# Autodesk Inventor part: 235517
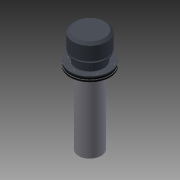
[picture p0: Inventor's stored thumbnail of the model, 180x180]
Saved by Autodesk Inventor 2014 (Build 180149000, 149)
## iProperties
Shininess: 20.0
Length Units: 11272
Angle Units: 11279
Time Units: 11290
Mass Units: 11286
Length Display Precision: 3
Angle Display Precision: 2
Company: Autodesk, Inc.
Created: 2002-06
Part Number: 235517
Material: AL 2024-T4
Description: FILLER BREATHER
Document SubType Name: Modeling
Designer: Autodesk, Inc.
Density: 2.78 g/cm^3
Mass: 669.093 g
Surface Area: 882.995 cm^2
Volume: 240.681 cm^3
Appearance: Metal-AL-6061(Flat)
Density: 0.0
Volumn: 0.0
Area: 0.0
PropertySet Name: Model Information
Control State: 0
Master: False
Checked Out: False
Last Check In By: JT
Last Check In Date: 2003-06-20
Title: FILLER BREATHER
Author: Autodesk, Inc.
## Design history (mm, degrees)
sketch "Sketch1"
  geometry: L1 (0, 0)-(0, -187.41); L2 (0, -169.863)-(0, -169.863); L3 (0, 0)-(-41.275, 0); L4 (-41.275, 0)-(-41.275, 2.381); L5 (-41.275, 2.381)-(-28.575, 2.381); L6 (-28.575, 2.381)-(-28.575, 15.081); L7 (-28.575, 15.081)-(-27.781, 15.081); L8 (-27.781, 15.081)-(-27.781, 18.256); L9 (-27.781, 18.256)-(-33.338, 18.256); L10 (-33.338, 18.256)-(-33.338, 21.431); L11 (-33.338, 21.431)-(-22.225, 21.431); L12 (-22.225, 21.431)-(-22.225, 24.606); L13 (-22.225, 24.606)-(-34.925, 24.606); L14 (-34.925, 24.606)-(-34.925, 53.181); L15 (-34.925, 53.181)-(-30.162, 57.944); L16 (-30.162, 57.944)-(0, 57.944); L17 (0, 57.944)-(0, 0); L18 (0, 0)-(0, 124.882)
  constraints: 36 end point, 10 parallel, 4 perpendicular, 2 collinear, 1 vertical, 1 vertical alignment
  dimensions: "d11" = 2.38125 distance of L3.end L4.end; "d12" = 12.7 distance of L5.end L6.end; "d13" = 3.175 distance of L7.end L8.end; "d14" = 3.175 distance of L9.end L10.end; "d15" = 3.175 distance of L11.end L12.end; "d16" = 33.3375 distance between parallel lines of L16 L13; "d17" = 4.7625 horizontal distance of L14.end L15.end; "d18" = 45 deg angle of L16 L15; "d19" = 57.15 diameter of L6 L1; "d20" = 55.5625 diameter of L8 L1; "d21" = 66.675 diameter of L10 L1; "d22" = 44.45 diameter of L12 L1; "d23" = 69.85 diameter of L14 L18; "d35" = 82.55 diameter of L4 L1
revolve "Revolution1" sketch "Sketch1" stored, may be unused: angle "d24" = 90 deg
sketch "Sketch2"
  geometry: L1 (-3.175, 41.275)-(-4.763, 41.275); L2 (-4.763, 41.275)-(-4.763, 23.813); L3 (-4.763, 23.813)-(-157.162, 23.812); L4 (-160.337, 20.637)-(-160.338, 0); L5 (-160.338, 0)-(-159.322, 0); L6 (-159.322, 0)-(-159.322, 20.51); L7 (-157.036, 22.796)-(-3.175, 22.797); L8 (-3.175, 22.797)-(-3.175, 41.275); L9 (0, 0)-(-147.629, 0); A1 r 3.175 centre (-157.162, 20.637) between (-157.162, 23.812) and (-160.337, 20.637); A2 r 2.286 centre (-157.036, 20.51) between (-157.036, 22.796) and (-159.322, 20.51)
  constraints: 18 end point, 5 parallel, 4 point on circle, 4 tangent, 3 perpendicular, 2 centre point, 1 horizontal, 1 horizontal alignment
  dimensions: "d25" = 3.175 radius of A1; "d26" = 2.286 radius of A2; "d27" = 1.016 distance between parallel lines of L4 L6; "d28" = 1.016 distance between parallel lines of L3 L7; "d29" = 1.5875 distance between parallel lines of L8 L2; "d30" = 3.175 distance from line of L9.start L8; "d31" = 82.55 diameter of L1 L9; "d32" = 47.625 diameter of L3 L9; "d33" = 155.575 distance between parallel lines of L2 L4
revolve "Revolution2" sketch "Sketch2" stored, may be unused: angle "d34" = 90 deg
sketch "Sketch3"
  geometry: L1 (0, -41.275)-(0, 41.275) reference; L2 (-3.175, -41.275)-(-3.175, 41.275) reference; L3 (0, 0)-(-23.797, 0); L4 (-3.175, 41.25)-(-3.175, 28.55); L5 (-3.175, 28.55)-(0, 28.55); L6 (-7.938, 41.25)-(-7.938, 28.55); L7 (-7.938, 28.55)-(-3.175, 28.55); L8 (-7.938, 41.25)-(-3.175, 41.25); L9 (0, 28.55)-(0, 41.25); L10 (-3.175, 41.25)-(0, 41.25); L11 (-4.762, -41.275)-(-4.763, 41.275) reference; L12 (-4.763, 41.275)-(-3.175, 41.275) reference; L13 (-4.763, 41.275)-(-3.175, 41.275) reference; L14 (-4.763, 41.275)-(-3.175, 41.275) reference; 2 further points
  constraints: 16 end point, 6 perpendicular, 3 point on line, 2 collinear, 1 horizontal alignment, 1 parallel, 1 other
  dimensions: "d36" = 3.175 distance of L1.end L4.start; "d41" = 0.0254 distance from line of L2.end L8; "d42" = 12.7 distance of L6.start L6.end; "d54" = 3.175 distance between parallel lines of L11 L6
revolve "Revolution3" sketch "Sketch3" stored, may be unused: angle "d39" = 90 deg
sketch "Sketch4"
  geometry: C1 r 28.575 at (0, 0) reference; 1 further point
  constraints: 1 vertical alignment
  dimensions: "d55" = 35.71875 distance of point (0, -35.719) C1.centre
hole "Hole1" sketch "Sketch4" at (0, -35.719) diameter "d44" = 6.35; stored, may be unused: countersink angle "d48" = 82 deg, drill point angle "d50" = 118 deg; dims "d45" = 12.7, "d46" = 9.525, "d47" = 6.35, "d49" = 19.05
pattern_circular "Circular Pattern1" dims angle "d53" = 360 deg
body "Solid1"
